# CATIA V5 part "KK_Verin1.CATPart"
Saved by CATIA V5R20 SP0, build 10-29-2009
Part number: Verin1
Bounding box of the stored display mesh (mm): x -55.29 to -25.944, y 65.499 to 91.429, z -5 to 66.37
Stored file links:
  G:\Khaled_CFAO_2011\ST2M\ST2M_GR1\msallin\Khaled\Version_Finale\KK_Verin1.CATPart
  C:\Users\Mathieu\Desktop\Think Motion\JOUG-MELEE2.CATProduct
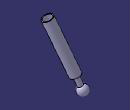
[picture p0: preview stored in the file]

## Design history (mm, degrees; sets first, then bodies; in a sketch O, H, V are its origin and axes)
External parameters (linked from other documents)
  `External.Taille du joug` = 100 mm
  `External.Taille du joug` = 100 mm
Set1
  Line1: linked copy from another document
  Line2: linked copy from another document
  Point1: linked copy from another document
Set2
  Plane1: type 2Lines, Element1 Line1, Element2 Line2
  Plane2: type 2Lines, Element1 Sketch1.L5, Element2 Sketch1.L1
  Point2: type Center, Curve Sketch1
  DatumSurface1
  Plane3: type OffsetPt, RefPlane Plane2, RefPoint Sketch1.P10
Body1 (main body)
  Sketch1 on Plane1, origin (-0.277, 81.5078, 20.3771), H (-1, -0.0034, 0), V (0.0008, -0.2425, 0.9701)
    point P1 (35.2994, 46.9337)
    line L1 (35.2994, 46.9337) -> (50.7679, -5.8463)
    line L2 (50.7679, -5.8463) -> (48.3688, -6.5494)
    line L3 (48.3688, -6.5494) -> (51.1813, -16.1457)
    arc A1 centre (50, -21.0042) radius 5 from (51.4062, -25.8024) to (51.1813, -16.1457) ccw
    point P5 (50, -21.0042)
    point P6 (51.4062, -25.8024)
    line L4 (35.2994, 46.9337) -> (34.4997, 46.6993)
    line L5 (34.4997, 46.6993) -> (46.8745, 4.4754)
    point P8 (46.8745, 4.4754)
    line L6 (46.8745, 4.4754) -> (42.876, 3.3035)
    point P9 (46.8745, 4.4754)
    point P10 (42.876, 3.3035)
    reference projected line E1 (19.7906, 82.0734) -> (50, -21.0042) from Line2
    reference projected line E2 (19.7906, 82.0734) -> (50, -21.0042) from Line2
    reference projected point E3 (50, -21.0042) from Point1
    reference projected line E4 (19.7906, 82.0734) -> (50, -21.0042) from Line2
    reference projected line E5 (19.7906, 82.0734) -> (50, -21.0042) from Line2
    length L1 = 55 {= `External.Taille du joug` *(7/10-1/10-1/20)}
    length L5 = 44 {= Sketch1.length(L1) *4/5}
    distance P1 E1 = 5 {= `External.Taille du joug` /20}
    length L2 = 2.5 {= `External.Taille du joug` /40}
    distance P10 E2 = 0
    length L3 = 10 {= `External.Taille du joug` /10}
    radius A1 = 5 {= `External.Taille du joug` /20}
    distance P5 E3 = 0
    distance L5 E4 = 4.1667 {= `External.Taille du joug` /24}
    distance E5 P6 = 0
    perpendicularity: L2 L1
    parallelism: L3 L1, L4 L2, L5 L1, L6 L2
    coincidence: P9 P8
  Shaft1: profile Sketch1, axis Line2, angle 360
